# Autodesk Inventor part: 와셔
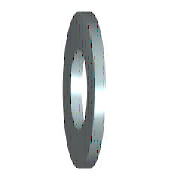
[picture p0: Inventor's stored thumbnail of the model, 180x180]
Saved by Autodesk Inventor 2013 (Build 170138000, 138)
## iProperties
Created: 2012-02
Part Number: 와셔
Material: 스테인리스강
Description: 평면 와셔 - 대형 시리즈 - 제품 등급 A
Document SubType Name: Modeling
Standard: ISO 7093 A
Designer: mduedu
Standard Revision: First Edition 2000-06-01
Standards Organization: ISO
Language: ko-KR
Size Designation: ST 3 - 140 HV - A
Categories: <MemberInstance><Categories><Category DisplayName="조임쇠" InternalName="e4da775c-781d-43d5-af7c-5136215cf5a6" Mnemonic="FSTN"><Category DisplayName="와셔" InternalN
Density: 8.08 g/cm^3
Mass: 0.359235 g
Surface Area: 1.41811 cm^2
Volume: 0.0444598 cm^3
IsCustomPart: 1
Author: mduedu
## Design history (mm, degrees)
sketch "스케치"
  geometry: C1 r 4.5 at (0, 0); C2 r 1.6 at (0, 0); 1 further point
  constraints: 2 centre point, 2 coincident
  dimensions: "d0" = 3.2 diameter of C2 (= SD1); "d1" = 9 diameter of C1 (= SD2)
extrude "본체" new body sketch "스케치" distance "d2" = 0.8 (= SD); taper "d3" = 0 deg
workaxis "Work Axis1"
workplane "Work Plane1"
sketch "스케치5"
  geometry: 2 further points
  constraints: 1 coincident
body "Solid1"
other parameters: "SD1" = 3.2 [user parameter; used in 1 equation term], "SD2" = 9 [user parameter; used in 1 equation term], "SD" = 0.8 [user parameter; used in 1 equation term], "d4" = 0, "d5" = 0, "d6" = 0, "d7" = 0, "NND" = 3 [user parameter]
